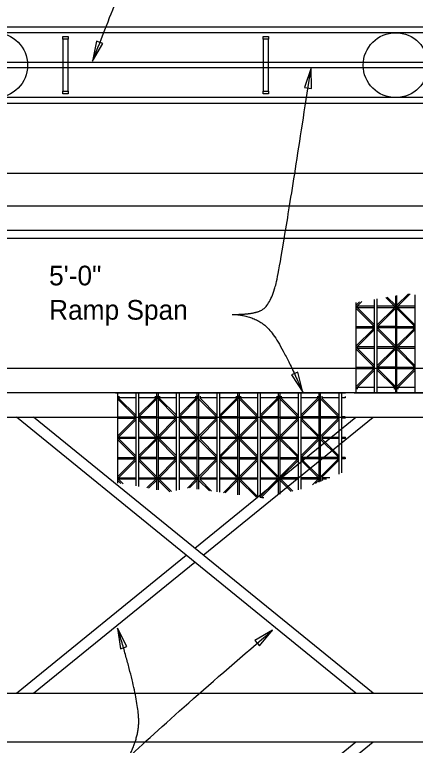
# Model space of a CAD drawing. Extents: x 10618 to 10724, y 76431 to 76484.
# Drawn here: x 10649.06 to 10655.23, y 76464.26 to 76475.51 of the extents above; entities that cross this region are included whole.
import ezdxf

# ---------------------------------------------------------------- set-up
doc = ezdxf.new("R2010")
doc.units = 0
for name, color, linetype in [('CL_Minor', 7, 'Continuous'), ('Dimension', 7, 'Continuous'), ('SteelMisc', 7, 'Continuous'), ('SteelMisc_h', 7, 'Continuous'), ('TextStructures', 7, 'Continuous'), ('Wood_h', 7, 'Continuous')]:
    doc.layers.add(name, color=color, linetype=linetype)

msp = doc.modelspace()

# ---------------------------------------------------------------- linework, layer by layer
at = {"layer": 'CL_Minor'}
for points in [[(10632.005, 76472.56), (10665.499, 76472.56)], [(10633.601, 76472.185), (10663.013, 76472.185), (10663.926, 76472.185)]]:
    msp.add_lwpolyline(points, dxfattribs=at)
at = {"layer": 'Dimension'}
for points in [[(10650.262, 76474.787), (10650.424, 76475.06), (10650.325, 76475.098)], [(10653.627, 76474.684), (10653.527, 76474.383), (10653.632, 76474.367)], [(10653.499, 76469.692), (10653.425, 76470), (10653.327, 76469.959)], [(10650.65, 76466.059), (10650.692, 76465.745), (10650.793, 76465.777)], [(10653.036, 76466.033), (10652.764, 76465.87), (10652.833, 76465.79)]]:
    msp.add_lwpolyline(points, close=True, dxfattribs=at)
for points in [[(10652.384, 76477.446), (10651.46, 76477.446), (10651.046, 76476.821), (10650.262, 76474.787)], [(10650.033, 76462.379), (10649.734, 76462.379), (10649.531, 76463.039), (10653.036, 76466.033)], [(10650.607, 76463.726), (10650.975, 76464.246), (10650.975, 76465.012), (10650.65, 76466.059)]]:
    msp.add_open_spline(points, degree=2, dxfattribs=at)
at = {"layer": 'SteelMisc'}
for p, q in [((10660.764, 76474.769), (10636.764, 76474.769)), ((10660.764, 76474.685), (10636.764, 76474.685)), ((10660.764, 76469.686), (10636.764, 76469.686))]:
    msp.add_line(p, q, dxfattribs=at)
at = {"layer": 'SteelMisc_h'}
for p, q in [((10654.925, 76471.178), (10654.925, 76469.686)), ((10654.946, 76471.031), (10655.126, 76471.21)), ((10654.946, 76469.686), (10654.946, 76471.182)), ((10655.151, 76471.205), (10654.967, 76471.022)), ((10655.228, 76469.686), (10655.228, 76471.19)), ((10654.321, 76471.031), (10654.375, 76471.084)), ((10654.321, 76469.686), (10654.321, 76471.076)), ((10654.409, 76471.089), (10654.342, 76471.022)), ((10654.603, 76469.686), (10654.603, 76471.122)), ((10654.644, 76469.686), (10654.644, 76471.129)), ((10654.776, 76471.152), (10654.905, 76471.024)), ((10654.801, 76471.157), (10654.925, 76471.032)), ((10654.321, 76470.981), (10654.398, 76470.904)), ((10654.582, 76470.72), (10654.321, 76470.981)), ((10654.342, 76470.99), (10654.342, 76471.022)), ((10654.602, 76470.729), (10654.342, 76470.99)), ((10654.602, 76471.016), (10654.343, 76471.016)), ((10654.343, 76470.995), (10654.603, 76470.995)), ((10654.902, 76471.016), (10654.643, 76471.016)), ((10654.644, 76470.728), (10654.905, 76470.988)), ((10654.646, 76470.995), (10654.905, 76470.995)), ((10654.665, 76470.719), (10654.925, 76470.98)), ((10654.905, 76471.024), (10654.905, 76470.99)), ((10654.925, 76470.981), (10654.925, 76471.032)), ((10654.925, 76470.98), (10654.925, 76470.407)), ((10654.946, 76470.98), (10655.023, 76470.904)), ((10655.207, 76470.72), (10654.946, 76470.98)), ((10654.967, 76470.989), (10654.967, 76471.022)), ((10655.227, 76470.729), (10654.967, 76470.989)), ((10655.227, 76471.016), (10654.968, 76471.016)), ((10654.968, 76470.995), (10655.228, 76470.995)), ((10654.582, 76470.666), (10654.582, 76470.72)), ((10654.665, 76470.668), (10654.665, 76470.719)), ((10655.207, 76470.666), (10655.207, 76470.72)), ((10654.321, 76470.406), (10654.582, 76470.666)), ((10654.323, 76470.683), (10654.581, 76470.683)), ((10654.325, 76470.704), (10654.582, 76470.704)), ((10654.603, 76470.658), (10654.342, 76470.397)), ((10654.645, 76470.659), (10654.905, 76470.399)), ((10654.925, 76470.683), (10654.665, 76470.683)), ((10654.665, 76470.668), (10654.925, 76470.407)), ((10654.924, 76470.704), (10654.666, 76470.704)), ((10654.946, 76470.406), (10655.207, 76470.666)), ((10654.948, 76470.682), (10655.206, 76470.682)), ((10654.95, 76470.703), (10655.207, 76470.703)), ((10655.228, 76470.658), (10654.967, 76470.397)), ((10654.342, 76470.365), (10654.342, 76470.397)), ((10654.602, 76470.391), (10654.343, 76470.391)), ((10654.902, 76470.391), (10654.643, 76470.391)), ((10654.905, 76470.399), (10654.905, 76470.365)), ((10654.925, 76470.356), (10654.925, 76470.407)), ((10654.967, 76470.364), (10654.967, 76470.397)), ((10655.227, 76470.391), (10654.968, 76470.391)), ((10654.321, 76470.356), (10654.398, 76470.279)), ((10654.582, 76470.095), (10654.321, 76470.356)), ((10654.602, 76470.104), (10654.342, 76470.365)), ((10654.343, 76470.37), (10654.603, 76470.37)), ((10654.644, 76470.103), (10654.905, 76470.363)), ((10654.646, 76470.37), (10654.905, 76470.37)), ((10654.665, 76470.094), (10654.925, 76470.355)), ((10654.925, 76470.355), (10654.925, 76469.782)), ((10654.946, 76470.355), (10655.023, 76470.279)), ((10655.207, 76470.095), (10654.946, 76470.355)), ((10655.227, 76470.104), (10654.967, 76470.364)), ((10654.968, 76470.37), (10655.228, 76470.37)), ((10636.305, 76470.061), (10661.222, 76470.061)), ((10654.321, 76469.781), (10654.582, 76470.041)), ((10654.323, 76470.058), (10654.581, 76470.058)), ((10654.325, 76470.079), (10654.582, 76470.079)), ((10654.582, 76470.041), (10654.582, 76470.095)), ((10654.665, 76470.043), (10654.665, 76470.094)), ((10654.925, 76470.058), (10654.665, 76470.058)), ((10654.665, 76470.043), (10654.925, 76469.782)), ((10654.924, 76470.079), (10654.666, 76470.079)), ((10654.946, 76469.781), (10655.207, 76470.041)), ((10654.948, 76470.057), (10655.206, 76470.057)), ((10654.95, 76470.078), (10655.207, 76470.078)), ((10655.207, 76470.041), (10655.207, 76470.095)), ((10654.603, 76470.033), (10654.342, 76469.772)), ((10654.645, 76470.034), (10654.905, 76469.774)), ((10655.228, 76470.033), (10654.967, 76469.772)), ((10654.342, 76469.74), (10654.342, 76469.772)), ((10654.602, 76469.766), (10654.343, 76469.766)), ((10654.902, 76469.766), (10654.643, 76469.766)), ((10654.905, 76469.774), (10654.905, 76469.74)), ((10654.925, 76469.731), (10654.925, 76469.782)), ((10654.967, 76469.739), (10654.967, 76469.772)), ((10655.227, 76469.766), (10654.968, 76469.766)), ((10650.619, 76469.686), (10654.158, 76469.686)), ((10650.647, 76469.686), (10650.647, 76468.295)), ((10650.668, 76469.632), (10650.668, 76469.599)), ((10650.929, 76469.338), (10650.668, 76469.599)), ((10650.928, 76469.605), (10650.669, 76469.605)), ((10650.928, 76469.686), (10650.928, 76468.25)), ((10651.228, 76469.605), (10650.969, 76469.605)), ((10650.97, 76469.686), (10650.97, 76468.242)), ((10650.971, 76469.338), (10651.231, 76469.598)), ((10651.231, 76469.598), (10651.231, 76469.632)), ((10651.251, 76468.193), (10651.251, 76469.686)), ((10651.251, 76469.64), (10651.251, 76469.589)), ((10651.272, 76469.686), (10651.272, 76468.189)), ((10651.272, 76469.591), (10651.533, 76469.33)), ((10651.293, 76469.632), (10651.293, 76469.599)), ((10651.554, 76469.338), (10651.293, 76469.599)), ((10651.553, 76469.605), (10651.294, 76469.605)), ((10651.553, 76469.686), (10651.553, 76468.182)), ((10651.853, 76469.605), (10651.594, 76469.605)), ((10651.595, 76469.686), (10651.595, 76468.19)), ((10651.596, 76469.338), (10651.856, 76469.598)), ((10651.856, 76469.598), (10651.856, 76469.632)), ((10651.876, 76468.202), (10651.876, 76469.686)), ((10651.876, 76469.641), (10651.876, 76469.59)), ((10651.897, 76469.686), (10651.897, 76468.199)), ((10651.897, 76469.591), (10652.158, 76469.331)), ((10651.918, 76469.633), (10651.918, 76469.6)), ((10652.179, 76469.339), (10651.918, 76469.6)), ((10652.178, 76469.606), (10651.919, 76469.606)), ((10652.178, 76469.686), (10652.178, 76468.16)), ((10652.478, 76469.606), (10652.219, 76469.606)), ((10652.22, 76469.686), (10652.22, 76468.155)), ((10652.221, 76469.339), (10652.481, 76469.599)), ((10652.481, 76469.599), (10652.481, 76469.633)), ((10652.501, 76468.116), (10652.501, 76469.686)), ((10652.501, 76469.641), (10652.501, 76469.59)), ((10652.522, 76469.686), (10652.522, 76468.113)), ((10652.522, 76469.592), (10652.783, 76469.331)), ((10652.543, 76469.633), (10652.543, 76469.6)), ((10652.804, 76469.339), (10652.543, 76469.6)), ((10652.803, 76469.606), (10652.544, 76469.606)), ((10652.803, 76469.686), (10652.803, 76468.074)), ((10653.103, 76469.606), (10652.844, 76469.606)), ((10652.845, 76469.686), (10652.845, 76468.068)), ((10652.846, 76469.339), (10653.106, 76469.599)), ((10652.866, 76469.33), (10653.126, 76469.591)), ((10653.106, 76469.599), (10653.106, 76469.633)), ((10653.126, 76468.119), (10653.126, 76469.686)), ((10653.126, 76469.642), (10653.126, 76469.591)), ((10653.126, 76469.018), (10653.126, 76469.591)), ((10653.147, 76469.686), (10653.147, 76468.124)), ((10653.147, 76469.592), (10653.408, 76469.332)), ((10653.168, 76469.634), (10653.168, 76469.601)), ((10653.429, 76469.34), (10653.168, 76469.601)), ((10653.428, 76469.607), (10653.169, 76469.607)), ((10653.428, 76469.686), (10653.428, 76468.192)), ((10653.728, 76469.607), (10653.469, 76469.607)), ((10653.47, 76469.686), (10653.47, 76468.201)), ((10653.471, 76469.34), (10653.731, 76469.6)), ((10653.491, 76469.33), (10653.751, 76469.591)), ((10653.731, 76469.6), (10653.731, 76469.634)), ((10653.751, 76468.309), (10653.751, 76469.686)), ((10653.751, 76469.642), (10653.751, 76469.591)), ((10653.751, 76469.019), (10653.751, 76469.591)), ((10653.772, 76468.318), (10653.772, 76469.686)), ((10653.772, 76469.592), (10653.772, 76469.642)), ((10654.033, 76469.332), (10653.772, 76469.592)), ((10653.793, 76469.634), (10653.793, 76469.601)), ((10654.053, 76469.34), (10653.793, 76469.601)), ((10654.055, 76469.607), (10653.794, 76469.607)), ((10654.053, 76469.686), (10654.053, 76468.433)), ((10654.095, 76469.686), (10654.095, 76468.45)), ((10654.152, 76469.607), (10654.095, 76469.607)), ((10654.152, 76469.628), (10654.152, 76469.607)), ((10654.293, 76469.686), (10657.832, 76469.686)), ((10650.647, 76469.59), (10650.908, 76469.33)), ((10650.991, 76469.328), (10651.251, 76469.589)), ((10651.251, 76469.016), (10651.251, 76469.589)), ((10651.616, 76469.329), (10651.876, 76469.59)), ((10651.876, 76469.017), (10651.876, 76469.59)), ((10652.241, 76469.329), (10652.501, 76469.59)), ((10652.501, 76469.018), (10652.501, 76469.59)), ((10636.305, 76469.311), (10661.222, 76469.311)), ((10654.317, 76465.061), (10649.093, 76469.311)), ((10654.581, 76465.061), (10649.357, 76469.311)), ((10650.908, 76469.276), (10650.647, 76469.015)), ((10650.649, 76469.313), (10650.907, 76469.313)), ((10650.651, 76469.292), (10650.908, 76469.292)), ((10650.928, 76469.267), (10650.668, 76469.007)), ((10650.908, 76469.33), (10650.908, 76469.276)), ((10650.97, 76469.268), (10651.231, 76469.008)), ((10650.991, 76469.328), (10650.991, 76469.277)), ((10651.251, 76469.313), (10650.991, 76469.313)), ((10650.991, 76469.277), (10651.251, 76469.016)), ((10651.25, 76469.292), (10650.992, 76469.292)), ((10651.533, 76469.276), (10651.272, 76469.016)), ((10651.274, 76469.314), (10651.532, 76469.314)), ((10651.276, 76469.293), (10651.533, 76469.293)), ((10651.553, 76469.267), (10651.293, 76469.007)), ((10651.533, 76469.33), (10651.533, 76469.276)), ((10651.595, 76469.269), (10651.856, 76469.008)), ((10651.616, 76469.329), (10651.616, 76469.278)), ((10651.876, 76469.314), (10651.616, 76469.314)), ((10651.616, 76469.278), (10651.876, 76469.017)), ((10651.875, 76469.293), (10651.617, 76469.293)), ((10651.837, 76467.293), (10654.317, 76469.311)), ((10652.158, 76469.277), (10651.897, 76469.016)), ((10651.899, 76469.314), (10652.157, 76469.314)), ((10651.901, 76469.293), (10652.158, 76469.293)), ((10652.178, 76469.268), (10651.918, 76469.008)), ((10651.969, 76467.186), (10654.581, 76469.311)), ((10652.158, 76469.331), (10652.158, 76469.277)), ((10652.22, 76469.269), (10652.481, 76469.009)), ((10652.241, 76469.329), (10652.241, 76469.278)), ((10652.501, 76469.314), (10652.241, 76469.314)), ((10652.241, 76469.278), (10652.501, 76469.018)), ((10652.5, 76469.293), (10652.242, 76469.293)), ((10652.783, 76469.277), (10652.522, 76469.017)), ((10652.524, 76469.315), (10652.782, 76469.315)), ((10652.526, 76469.294), (10652.783, 76469.294)), ((10652.803, 76469.269), (10652.543, 76469.008)), ((10652.783, 76469.331), (10652.783, 76469.277)), ((10652.845, 76469.27), (10653.106, 76469.009)), ((10652.866, 76469.33), (10652.866, 76469.279)), ((10653.126, 76469.315), (10652.866, 76469.315)), ((10652.866, 76469.279), (10653.126, 76469.018)), ((10653.125, 76469.294), (10652.867, 76469.294)), ((10653.408, 76469.278), (10653.147, 76469.017)), ((10653.149, 76469.315), (10653.407, 76469.315)), ((10653.151, 76469.294), (10653.408, 76469.294)), ((10653.428, 76469.269), (10653.168, 76469.009)), ((10653.408, 76469.332), (10653.408, 76469.278)), ((10653.47, 76469.27), (10653.731, 76469.01)), ((10653.491, 76469.33), (10653.491, 76469.279)), ((10653.751, 76469.315), (10653.491, 76469.315)), ((10653.491, 76469.279), (10653.751, 76469.019)), ((10653.75, 76469.294), (10653.492, 76469.294)), ((10654.033, 76469.278), (10653.772, 76469.017)), ((10654.029, 76469.274), (10653.772, 76469.017)), ((10654.031, 76469.294), (10653.776, 76469.294)), ((10654.031, 76469.315), (10653.777, 76469.315)), ((10654.054, 76469.27), (10653.793, 76469.009)), ((10654.033, 76469.332), (10654.033, 76469.278)), ((10654.152, 76469.315), (10654.095, 76469.315)), ((10654.152, 76469.294), (10654.096, 76469.294)), ((10654.152, 76469.315), (10654.152, 76469.294)), ((10650.647, 76469.015), (10650.724, 76469.092)), ((10651.272, 76469.016), (10651.349, 76469.092)), ((10651.897, 76469.016), (10651.974, 76469.093)), ((10652.522, 76469.017), (10652.599, 76469.094)), ((10653.147, 76469.017), (10653.224, 76469.094)), ((10650.647, 76468.965), (10650.908, 76468.705)), ((10650.668, 76469.007), (10650.668, 76468.974)), ((10650.929, 76468.713), (10650.668, 76468.974)), ((10650.669, 76469.001), (10650.929, 76469.001)), ((10650.928, 76468.98), (10650.669, 76468.98)), ((10651.228, 76468.98), (10650.969, 76468.98)), ((10650.971, 76468.713), (10651.231, 76468.973)), ((10650.972, 76469.001), (10651.231, 76469.001)), ((10650.991, 76468.703), (10651.251, 76468.964)), ((10651.231, 76468.973), (10651.231, 76469.007)), ((10651.251, 76469.015), (10651.251, 76468.964)), ((10651.251, 76468.391), (10651.251, 76468.964)), ((10651.272, 76468.966), (10651.533, 76468.705)), ((10651.293, 76469.007), (10651.293, 76468.974)), ((10651.554, 76468.713), (10651.293, 76468.974)), ((10651.294, 76469.001), (10651.554, 76469.001)), ((10651.553, 76468.98), (10651.294, 76468.98)), ((10651.853, 76468.98), (10651.594, 76468.98)), ((10651.596, 76468.713), (10651.856, 76468.973)), ((10651.597, 76469.001), (10651.856, 76469.001)), ((10651.616, 76468.704), (10651.876, 76468.965)), ((10651.856, 76468.973), (10651.856, 76469.007)), ((10651.876, 76469.016), (10651.876, 76468.965)), ((10651.876, 76468.392), (10651.876, 76468.965)), ((10651.897, 76468.966), (10652.158, 76468.706)), ((10651.918, 76469.008), (10651.918, 76468.975)), ((10652.179, 76468.714), (10651.918, 76468.975)), ((10651.919, 76469.002), (10652.179, 76469.002)), ((10652.178, 76468.981), (10651.919, 76468.981)), ((10652.478, 76468.981), (10652.219, 76468.981)), ((10652.221, 76468.714), (10652.481, 76468.974)), ((10652.222, 76469.002), (10652.481, 76469.002)), ((10652.241, 76468.704), (10652.501, 76468.965)), ((10652.481, 76468.974), (10652.481, 76469.008)), ((10652.501, 76469.016), (10652.501, 76468.965)), ((10652.501, 76468.393), (10652.501, 76468.965)), ((10652.522, 76468.967), (10652.783, 76468.706)), ((10652.543, 76469.008), (10652.543, 76468.975)), ((10652.804, 76468.714), (10652.543, 76468.975)), ((10652.544, 76469.002), (10652.804, 76469.002)), ((10652.803, 76468.981), (10652.544, 76468.981)), ((10653.103, 76468.981), (10652.844, 76468.981)), ((10652.846, 76468.714), (10653.106, 76468.974)), ((10652.847, 76469.002), (10653.106, 76469.002)), ((10652.866, 76468.705), (10653.126, 76468.966)), ((10653.106, 76468.974), (10653.106, 76469.008)), ((10653.126, 76469.017), (10653.126, 76468.966)), ((10653.126, 76468.393), (10653.126, 76468.966)), ((10653.147, 76468.967), (10653.408, 76468.707)), ((10653.168, 76469.009), (10653.168, 76468.976)), ((10653.429, 76468.715), (10653.168, 76468.976)), ((10653.169, 76469.003), (10653.429, 76469.003)), ((10653.428, 76468.982), (10653.169, 76468.982)), ((10653.728, 76468.982), (10653.469, 76468.982)), ((10653.471, 76468.715), (10653.731, 76468.975)), ((10653.472, 76469.003), (10653.731, 76469.003)), ((10653.491, 76468.705), (10653.751, 76468.966)), ((10653.731, 76468.975), (10653.731, 76469.009)), ((10653.751, 76469.017), (10653.751, 76468.966)), ((10653.751, 76468.394), (10653.751, 76468.966)), ((10653.772, 76468.967), (10653.772, 76469.017)), ((10654.033, 76468.707), (10653.772, 76468.967)), ((10653.793, 76469.009), (10653.793, 76468.976)), ((10654.053, 76468.715), (10653.793, 76468.976)), ((10654.055, 76468.982), (10653.794, 76468.982)), ((10653.795, 76469.003), (10654.055, 76469.003)), ((10654.095, 76469.003), (10654.158, 76469.003)), ((10654.152, 76468.982), (10654.095, 76468.982)), ((10654.152, 76469.003), (10654.152, 76468.982)), ((10650.908, 76468.705), (10650.908, 76468.651)), ((10650.991, 76468.703), (10650.991, 76468.652)), ((10651.533, 76468.705), (10651.533, 76468.651)), ((10651.616, 76468.704), (10651.616, 76468.653)), ((10652.158, 76468.706), (10652.158, 76468.652)), ((10652.241, 76468.704), (10652.241, 76468.653)), ((10652.783, 76468.706), (10652.783, 76468.652)), ((10652.866, 76468.705), (10652.866, 76468.654)), ((10653.408, 76468.707), (10653.408, 76468.653)), ((10653.491, 76468.705), (10653.491, 76468.654)), ((10654.033, 76468.707), (10654.033, 76468.653)), ((10650.908, 76468.651), (10650.647, 76468.39)), ((10650.649, 76468.688), (10650.907, 76468.688)), ((10650.651, 76468.667), (10650.908, 76468.667)), ((10650.928, 76468.642), (10650.668, 76468.382)), ((10650.97, 76468.643), (10651.231, 76468.383)), ((10651.251, 76468.688), (10650.991, 76468.688)), ((10650.991, 76468.652), (10651.251, 76468.391)), ((10651.25, 76468.667), (10650.992, 76468.667)), ((10651.533, 76468.651), (10651.272, 76468.391)), ((10651.274, 76468.689), (10651.532, 76468.689)), ((10651.276, 76468.668), (10651.533, 76468.668)), ((10651.553, 76468.642), (10651.293, 76468.382)), ((10651.595, 76468.644), (10651.856, 76468.383)), ((10651.876, 76468.689), (10651.616, 76468.689)), ((10651.616, 76468.653), (10651.876, 76468.392)), ((10651.875, 76468.668), (10651.617, 76468.668)), ((10652.158, 76468.652), (10651.897, 76468.391)), ((10651.899, 76468.689), (10652.157, 76468.689)), ((10651.901, 76468.668), (10652.158, 76468.668)), ((10652.178, 76468.643), (10651.918, 76468.383)), ((10652.22, 76468.644), (10652.481, 76468.384)), ((10652.501, 76468.689), (10652.241, 76468.689)), ((10652.241, 76468.653), (10652.501, 76468.393)), ((10652.5, 76468.668), (10652.242, 76468.668)), ((10652.783, 76468.652), (10652.522, 76468.392)), ((10652.524, 76468.69), (10652.782, 76468.69)), ((10652.526, 76468.669), (10652.783, 76468.669)), ((10652.803, 76468.644), (10652.543, 76468.383)), ((10652.845, 76468.645), (10653.106, 76468.384)), ((10653.126, 76468.69), (10652.866, 76468.69)), ((10652.866, 76468.654), (10653.126, 76468.393)), ((10653.125, 76468.669), (10652.867, 76468.669)), ((10653.408, 76468.653), (10653.147, 76468.392)), ((10653.149, 76468.69), (10653.407, 76468.69)), ((10653.151, 76468.669), (10653.408, 76468.669)), ((10653.428, 76468.644), (10653.168, 76468.384)), ((10653.47, 76468.645), (10653.731, 76468.385)), ((10653.751, 76468.69), (10653.491, 76468.69)), ((10653.491, 76468.654), (10653.751, 76468.394)), ((10653.75, 76468.669), (10653.492, 76468.669)), ((10654.033, 76468.653), (10653.772, 76468.392)), ((10654.029, 76468.649), (10653.772, 76468.392)), ((10654.031, 76468.669), (10653.776, 76468.669)), ((10654.031, 76468.69), (10653.777, 76468.69)), ((10654.054, 76468.645), (10653.793, 76468.384)), ((10654.152, 76468.69), (10654.095, 76468.69)), ((10654.152, 76468.669), (10654.096, 76468.669)), ((10654.152, 76468.69), (10654.152, 76468.669)), ((10650.647, 76468.39), (10650.724, 76468.467)), ((10651.272, 76468.391), (10651.349, 76468.467)), ((10651.897, 76468.391), (10651.974, 76468.468)), ((10652.522, 76468.392), (10652.599, 76468.469)), ((10653.147, 76468.392), (10653.224, 76468.469)), ((10650.668, 76468.382), (10650.668, 76468.349)), ((10650.669, 76468.376), (10650.929, 76468.376)), ((10650.928, 76468.355), (10650.669, 76468.355)), ((10651.228, 76468.355), (10650.969, 76468.355)), ((10650.972, 76468.376), (10651.231, 76468.376)), ((10651.231, 76468.348), (10651.231, 76468.382)), ((10651.251, 76468.39), (10651.251, 76468.339)), ((10651.293, 76468.382), (10651.293, 76468.349)), ((10651.294, 76468.376), (10651.554, 76468.376)), ((10651.553, 76468.355), (10651.294, 76468.355)), ((10651.853, 76468.355), (10651.594, 76468.355)), ((10651.597, 76468.376), (10651.856, 76468.376)), ((10651.856, 76468.348), (10651.856, 76468.382)), ((10651.876, 76468.391), (10651.876, 76468.34)), ((10651.918, 76468.383), (10651.918, 76468.35)), ((10651.919, 76468.377), (10652.179, 76468.377)), ((10652.178, 76468.356), (10651.919, 76468.356)), ((10652.478, 76468.356), (10652.219, 76468.356)), ((10652.222, 76468.377), (10652.481, 76468.377)), ((10652.481, 76468.349), (10652.481, 76468.383)), ((10652.501, 76468.391), (10652.501, 76468.34)), ((10652.543, 76468.383), (10652.543, 76468.35)), ((10652.544, 76468.377), (10652.804, 76468.377)), ((10652.803, 76468.356), (10652.544, 76468.356)), ((10653.103, 76468.356), (10652.844, 76468.356)), ((10652.847, 76468.377), (10653.106, 76468.377)), ((10653.106, 76468.349), (10653.106, 76468.383)), ((10653.126, 76468.392), (10653.126, 76468.341)), ((10653.168, 76468.384), (10653.168, 76468.351)), ((10653.169, 76468.378), (10653.429, 76468.378)), ((10653.428, 76468.357), (10653.169, 76468.357)), ((10653.728, 76468.357), (10653.469, 76468.357)), ((10653.472, 76468.378), (10653.731, 76468.378)), ((10653.731, 76468.35), (10653.731, 76468.384)), ((10653.751, 76468.392), (10653.751, 76468.341)), ((10653.772, 76468.342), (10653.772, 76468.392)), ((10653.793, 76468.384), (10653.793, 76468.351)), ((10653.867, 76468.357), (10653.794, 76468.357)), ((10653.795, 76468.378), (10653.918, 76468.378)), ((10650.647, 76468.34), (10650.7, 76468.287)), ((10650.735, 76468.282), (10650.668, 76468.349)), ((10651.102, 76468.219), (10651.231, 76468.348)), ((10651.127, 76468.215), (10651.251, 76468.339)), ((10651.272, 76468.341), (10651.452, 76468.161)), ((10651.477, 76468.166), (10651.293, 76468.349)), ((10651.724, 76468.217), (10651.856, 76468.348)), ((10651.756, 76468.219), (10651.876, 76468.34)), ((10651.897, 76468.341), (10652.062, 76468.176)), ((10652.096, 76468.172), (10651.918, 76468.35)), ((10652.278, 76468.147), (10652.481, 76468.349)), ((10652.304, 76468.143), (10652.501, 76468.34)), ((10652.522, 76468.342), (10652.783, 76468.081)), ((10652.804, 76468.089), (10652.543, 76468.35)), ((10652.846, 76468.089), (10653.106, 76468.349)), ((10652.866, 76468.08), (10653.126, 76468.341)), ((10653.147, 76468.342), (10653.323, 76468.166)), ((10653.347, 76468.172), (10653.168, 76468.351)), ((10653.648, 76468.267), (10653.731, 76468.35)), ((10653.698, 76468.287), (10653.751, 76468.341)), ((10653.751, 76468.309), (10653.751, 76468.341)), ((10653.789, 76468.325), (10653.772, 76468.342)), ((10653.81, 76468.334), (10653.793, 76468.351)), ((10652.783, 76468.081), (10652.783, 76468.077)), ((10652.866, 76468.08), (10652.866, 76468.065)), ((10652.899, 76468.065), (10652.869, 76468.065)), ((10649.093, 76465.061), (10651.705, 76467.186)), ((10649.357, 76465.061), (10651.837, 76467.078)), ((10636.305, 76465.061), (10661.222, 76465.061)), ((10636.305, 76464.311), (10661.222, 76464.311)), ((10652.199, 76462.588), (10654.317, 76464.311)), ((10652.578, 76462.681), (10654.581, 76464.311))]:
    msp.add_line(p, q, dxfattribs=at)
for points in [[(10660.62, 76475.311), (10636.904, 76475.311)], [(10636.764, 76474.144), (10660.764, 76474.144)]]:
    msp.add_lwpolyline(points, dxfattribs=at)
for points in [[(10649.805, 76475.128), (10649.805, 76475.17), (10649.888, 76475.17), (10649.888, 76475.128)], [(10649.889, 76474.326), (10649.889, 76475.128), (10649.805, 76475.128), (10649.805, 76474.326)], [(10652.888, 76475.128), (10652.888, 76475.17), (10652.972, 76475.17), (10652.972, 76475.128)], [(10652.972, 76474.326), (10652.972, 76475.128), (10652.888, 76475.128), (10652.888, 76474.326)], [(10649.805, 76474.285), (10649.805, 76474.326), (10649.889, 76474.326), (10649.889, 76474.285)], [(10652.888, 76474.285), (10652.888, 76474.326), (10652.972, 76474.326), (10652.972, 76474.285)]]:
    msp.add_lwpolyline(points, close=True, dxfattribs=at)
at = {"layer": 'TextStructures'}
for points in [[(10652.413, 76470.89), (10652.796, 76470.89), (10653.004, 76471.066), (10653.155, 76471.585), (10653.627, 76474.684)], [(10652.413, 76470.89), (10652.692, 76470.89), (10653.123, 76470.571), (10653.499, 76469.692)]]:
    msp.add_open_spline(points, degree=2, dxfattribs=at)
at = {"layer": 'Wood_h'}
for p, q in [((10662.639, 76475.227), (10634.926, 76475.227)), ((10662.663, 76474.227), (10634.926, 76474.227)), ((10660.568, 76473.06), (10636.927, 76473.06)), ((10660.568, 76472.06), (10636.927, 76472.06))]:
    msp.add_line(p, q, dxfattribs=at)
for centre in [(10648.764, 76474.727), (10654.93, 76474.727)]:
    msp.add_circle(centre, 0.5, dxfattribs=at)

# ---------------------------------------------------------------- texts
at = {"layer": 'Dimension'}
for s, p in [('5\'-0" ', (10649.595, 76471.338)), ('Ramp Span', (10649.595, 76470.81))]:
    msp.add_text(s, height=0.3024, dxfattribs=at).set_placement(p)

doc.saveas('drawing.dxf')
